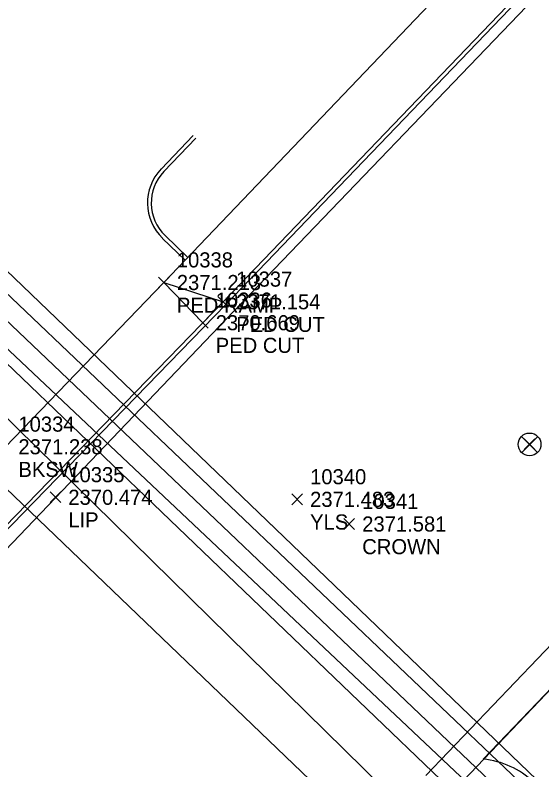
# Model space of a CAD drawing. Extents: x 2377639 to 2379738, y 729875 to 732734.
# Drawn here: x 2378926.7 to 2378996.4, y 731168.7 to 731268.8 of the extents above; entities that cross this region are included whole.
import ezdxf

# ---------------------------------------------------------------- set-up
doc = ezdxf.new("R2010")
doc.units = 0
for name, color, linetype in [('Default', 7, 'Continuous'), ('TOPO_CURBGTR_Back-of-Curb', 7, 'Continuous'), ('TOPO_CURBGTR_Face-of-Curb', 7, 'Continuous'), ('TOPO_CURBGTR_Lip-of-Gutter', 7, 'Continuous'), ('TOPO_DATA_Elevations', 7, 'Continuous'), ('TOPO_ELEC_Cable_Overhead-Exist', 7, 'Continuous'), ('TOPO_GAS_Line', 7, 'Continuous'), ('TOPO_GEOLOGY_Test-Hole', 7, 'Continuous'), ('TOPO_SAN_Plastic-Pipe', 7, 'Continuous'), ('TOPO_STORM_Line-Other', 7, 'Continuous'), ('TOPO_SW_Back', 7, 'Continuous'), ('TOPO_TELE_Overhead-Line', 7, 'Continuous'), ('TOPO_TELE_Underground-FO-Cable', 7, 'Continuous'), ('TOPO_TV_Cable-Overhead', 7, 'Continuous')]:
    doc.layers.add(name, color=color, linetype=linetype)

# ---------------------------------------------------------------- blocks, each defined once
blk = doc.blocks.new('BORE_1')
at = {"layer": 'Default'}
for p, q in [((-0.135, 0.129), (0.135, -0.139)), ((0.137, 0.13), (-0.13, -0.142))]:
    blk.add_line(p, q, dxfattribs=at)
blk.add_circle((0.001, -0.003), 0.191, dxfattribs=at)

msp = doc.modelspace()

# ---------------------------------------------------------------- linework, layer by layer
at = {"layer": 'TOPO_CURBGTR_Back-of-Curb'}
for p, q in [((2378946.37, 731248.05), (2378950.62, 731252.48)), ((2378949.55, 731236.68), (2378946.54, 731239.56))]:
    msp.add_line(p, q, dxfattribs=at)
msp.add_lwpolyline([(2378840.2, 731111.44), (2378906.5, 731181.63), (2378954.24, 731230.8), (2378996.06, 731274.46), (2379017.15, 731296.55), (2379025.13, 731304.84)], dxfattribs=at)
msp.add_arc((2378950.7, 731243.9), 6, 136.2032, 226.2032, dxfattribs=at)
at = {"layer": 'TOPO_CURBGTR_Face-of-Curb'}
for p, q in [((2378950.26, 731252.83), (2378946, 731248.39)), ((2378946.2, 731239.2), (2378949.21, 731236.32))]:
    msp.add_line(p, q, dxfattribs=at)
msp.add_lwpolyline([(2378840.55, 731111.08), (2378906.86, 731181.29), (2378954.6, 731230.45), (2378996.42, 731274.11), (2379017.51, 731296.21), (2379025.49, 731304.49)], dxfattribs=at)
msp.add_arc((2378950.7, 731243.9), 6.5, 136.2032, 226.2032, dxfattribs=at)
at = {"layer": 'TOPO_CURBGTR_Lip-of-Gutter'}
for p, q in [((2378981.07, 731167.99), (2379018.48, 731207.18)), ((2378988.67, 731170.16), (2379011.77, 731194.38))]:
    msp.add_line(p, q, dxfattribs=at)
msp.add_lwpolyline([(2378843.13, 731111.73), (2378912.12, 731183.98), (2378955.61, 731229.49), (2378997.65, 731273.38), (2379018.59, 731295.17), (2379029.35, 731306.31)], dxfattribs=at)
msp.add_arc((2378987.69, 731159.2), 11, 46.2211, 84.8948, dxfattribs=at)
at = {"layer": 'TOPO_DATA_Elevations'}
for p, q in [((2378945.68, 731232.65), (2378947.09, 731234.06)), ((2378945.68, 731234.06), (2378947.09, 731232.65)), ((2378953.53, 731230.09), (2378954.95, 731231.51)), ((2378953.53, 731231.51), (2378954.95, 731230.09)), ((2378950.83, 731227.32), (2378952.24, 731228.73)), ((2378950.83, 731228.73), (2378952.24, 731227.32)), ((2378994.09, 731211.21), (2378995.5, 731212.63)), ((2378994.09, 731212.63), (2378995.5, 731211.21)), ((2378931.3, 731204.18), (2378932.72, 731205.59)), ((2378931.3, 731205.59), (2378932.72, 731204.18)), ((2378963.32, 731203.9), (2378964.74, 731205.32)), ((2378963.32, 731205.32), (2378964.74, 731203.9)), ((2378970.22, 731200.63), (2378971.64, 731202.05)), ((2378970.22, 731202.05), (2378971.64, 731200.63))]:
    msp.add_line(p, q, dxfattribs=at)
at = {"layer": 'TOPO_ELEC_Cable_Overhead-Exist'}
for p, q in [((2379082.38, 731082.46), (2378871.59, 731283.35)), ((2379080.54, 731080.57), (2378869.76, 731281.46))]:
    msp.add_line(p, q, dxfattribs=at)
at = {"layer": 'TOPO_GAS_Line'}
msp.add_line((2378817.91, 731309.25), (2379078.96, 731058.81), dxfattribs=at)
at = {"layer": 'TOPO_SAN_Plastic-Pipe'}
msp.add_line((2379189.26, 730956.35), (2378923.42, 731217.48), dxfattribs=at)
at = {"layer": 'TOPO_STORM_Line-Other'}
msp.add_line((2379116.84, 731304.52), (2378950.77, 731130.35), dxfattribs=at)
at = {"layer": 'TOPO_SW_Back'}
msp.add_line((2378951.54, 731228.02), (2378946.38, 731233.35), dxfattribs=at)
for points in [[(2378946.38, 731233.35), (2378990.1, 731279.2), (2378993.42, 731282.56)], [(2378905.53, 731190.63), (2378925.4, 731211.58), (2378946.38, 731233.35), (2378954.24, 731230.8)]]:
    msp.add_lwpolyline(points, dxfattribs=at)
at = {"layer": 'TOPO_TELE_Overhead-Line'}
msp.add_line((2379079.4, 731079.39), (2378867.97, 731279.01), dxfattribs=at)
at = {"layer": 'TOPO_TELE_Underground-FO-Cable'}
msp.add_line((2379033.97, 731118.6), (2378867.09, 731278.7), dxfattribs=at)
at = {"layer": 'TOPO_TV_Cable-Overhead'}
msp.add_line((2379199.34, 730971.87), (2378747.39, 731406.04), dxfattribs=at)

# ---------------------------------------------------------------- block references
at = {"layer": 'TOPO_GEOLOGY_Test-Hole', "xscale": 7.8740000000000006, "yscale": 7.8740000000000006}
msp.add_blockref('BORE_1', (2378994.8, 731211.92), dxfattribs=at)

# ---------------------------------------------------------------- texts
at = {"layer": 'TOPO_DATA_Elevations'}
for s, p in [('10338', (2378948.09, 731235.35)), ('10337', (2378955.95, 731232.8)), ('2371.213', (2378948.09, 731232.35)), ('10336', (2378953.24, 731230.02)), ('2371.154', (2378955.95, 731229.8)), ('PED RAMP', (2378948.09, 731229.35)), ('2370.669', (2378953.24, 731227.02)), ('PED CUT', (2378955.95, 731226.8)), ('PED CUT', (2378953.24, 731224.02)), ('10334', (2378927.11, 731213.58)), ('2371.238', (2378927.11, 731210.58)), ('BKSW', (2378927.11, 731207.58)), ('10335', (2378933.72, 731206.88)), ('10340', (2378965.74, 731206.61)), ('2370.474', (2378933.72, 731203.88)), ('2371.483', (2378965.74, 731203.61)), ('10341', (2378972.64, 731203.34)), ('LIP', (2378933.72, 731200.88)), ('YLS', (2378965.74, 731200.61)), ('2371.581', (2378972.64, 731200.34)), ('CROWN', (2378972.64, 731197.34))]:
    msp.add_text(s, height=2, dxfattribs=at).set_placement(p)

doc.saveas('drawing.dxf')
